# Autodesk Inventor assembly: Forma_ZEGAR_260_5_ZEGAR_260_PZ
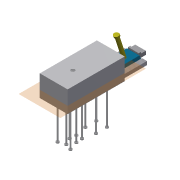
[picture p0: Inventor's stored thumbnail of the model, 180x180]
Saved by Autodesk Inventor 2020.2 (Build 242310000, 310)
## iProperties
Created: 2015-01
Part Number: Forma_ZEGAR_260_5_ZEGAR_260_PZ
Document SubType Name: Assembly
Designer: F.Stasiak
Catalog Web Link: www.expertbooks.pl
Manager: www.cadconsulting.pl
Company: Fabian Stasiak CAD Consulting
Author: F.Stasiak
Subject: Zbiór ćwiczeń. Autodesk Inventor 2020. Kurs Professional
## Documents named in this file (21)
- C:\2020_Kurs_Professional\R6 Formy\Komponenty\Forma_ZEGAR_260_5_ZEGAR_260_PZ.iam
- C:\2020_Kurs_Professional\R6 Formy\Komponenty\Forma_ZEGAR_260_5_ZEGAR_260_MP.ipt
- C:\2020_Kurs_Professional\R6 Formy\Komponenty\Forma_ZEGAR_260_5_ZEGAR_260_WP.ipt
- C:\2020_Kurs_Professional\R6 Formy\Komponenty\Forma_ZEGAR_260_5_ZEGAR_260_CR_Base.ipt
- C:\2020_Kurs_Professional\R6 Formy\Komponenty\Forma_ZEGAR_260_5_ZEGAR_260_CV_Base.ipt
- C:\2020_Kurs_Professional\R6 Formy\Komponenty\Rdzenie formujące\PUNCH_CDH\Forma_ZEGAR_260_5_ZEGAR_260_Rdzeń formujący2_Base.ipt
- C:\2020_Kurs_Professional\R6 Formy\Komponenty\Rdzenie formujące\PUNCH_CDH\Forma_ZEGAR_260_5_ZEGAR_260_Rdzeń formujący2_1.ipt
- C:\2020_Kurs_Professional\R6 Formy\Komponenty\Forma_ZEGAR_260_5_ZEGAR_260_IN1_Base.ipt
- C:\2020_Kurs_Professional\R6 Formy\Komponenty\Forma_ZEGAR_260_5_ZEGAR_260_IN1_1_1.ipt
- C:\2020_Kurs_Professional\R6 Formy\Komponenty\Wypychacze\DME_AH\Grupa EP1.0\Forma_ZEGAR_260_4_ZEGAR_260_Grupa EP1_EP1.ipt
- C:\2020_Kurs_Professional\R6 Formy\Komponenty\Wypychacze\DME_AH\Grupa EP1.0\Forma_ZEGAR_260_4_ZEGAR_260_Grupa EP1_EP2.ipt
- C:\2020_Kurs_Professional\R6 Formy\Komponenty\Wypychacze\DME_AH\Grupa EP1.0\Forma_ZEGAR_260_4_ZEGAR_260_Grupa EP1_EP3.ipt
- C:\2020_Kurs_Professional\R6 Formy\Komponenty\Wypychacze\DME_AH\Grupa EP1.0\Forma_ZEGAR_260_4_ZEGAR_260_Grupa EP1_EP4.ipt
- C:\2020_Kurs_Professional\R6 Formy\Komponenty\Wypychacze\DME_AH\Grupa EP1.0\Forma_ZEGAR_260_4_ZEGAR_260_Grupa EP1_EP5.ipt
- C:\2020_Kurs_Professional\R6 Formy\Komponenty\Wypychacze\DME_AH\Grupa EP1.0\Forma_ZEGAR_260_4_ZEGAR_260_Grupa EP1_EP6.ipt
- C:\2020_Kurs_Professional\R6 Formy\Komponenty\Wypychacze\DME_AH\Grupa EP1.0\Forma_ZEGAR_260_4_ZEGAR_260_Grupa EP1_EP7.ipt
- C:\2020_Kurs_Professional\R6 Formy\Komponenty\Wypychacze\DME_AH\Grupa EP1.0\Forma_ZEGAR_260_4_ZEGAR_260_Grupa EP1_EP8.ipt
- C:\2020_Kurs_Professional\R6 Formy\Komponenty\Wypychacze\DME_AH\Grupa EP1.0\Forma_ZEGAR_260_4_ZEGAR_260_Grupa EP1_EP9.ipt
- C:\2020_Kurs_Professional\R6 Formy\Komponenty\Wypychacze\DME_AH\Grupa EP1.0\Forma_ZEGAR_260_4_ZEGAR_260_Grupa EP1_EP10.ipt
- C:\2020_Kurs_Professional\R6 Formy\Komponenty\Wypychacze\DME_AH\Grupa EP1.0\Forma_ZEGAR_260_4_ZEGAR_260_Grupa EP1_EP11.ipt
- C:\2020_Kurs_Professional\R6 Formy\Komponenty\Suwaki\GENERIC_Zwykła blokada pojedyncza 1 1\Forma_ZEGAR_260_4_ZEGAR_260_SA1.iam
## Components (20 placed, 20 different names)
1. Forma_ZEGAR_260_4_ZEGAR_260_MP:1 — Równoległy:1, Równoległy:2, Równoległy:3, Równoległy:4, Równoległy:5, Równoległy:6
2. Forma_ZEGAR_260_4_ZEGAR_260_WP:1 — Równoległy:4, Równoległy:5, Równoległy:6
3. Forma_ZEGAR_260_4_ZEGAR_260_CR_Base:1 — Równoległy:7, Równoległy:8, Równoległy:9
4. Forma_ZEGAR_260_4_ZEGAR_260_CV_Base:1 — Równoległy:10, Równoległy:11, Równoległy:12
5. Forma_ZEGAR_260_4_ZEGAR_260_Rdzeń formujący2_Base:1 — Kąt:1, Równoległy:20, Równoległy:21, Równoległy:22, Równoległy:23
6. Forma_ZEGAR_260_4_ZEGAR_260_Rdzeń formujący2_1:1 — Równoległy:20, Równoległy:21, Równoległy:22
7. Forma_ZEGAR_260_4_ZEGAR_260_IN1_Base:1 — Równoległy:24, Równoległy:25, Równoległy:26, Równoległy:27, Równoległy:28, Równoległy:29
8. Forma_ZEGAR_260_4_ZEGAR_260_IN1_1_1:1 — Równoległy:27, Równoległy:28, Równoległy:29, Zestawiający:13
9. Forma_ZEGAR_260_4_ZEGAR_260_Grupa EP1_EP1:1 — Zestawiający:2, Równoległy:30, Kąt:2
10. Forma_ZEGAR_260_4_ZEGAR_260_Grupa EP1_EP2:1 — Zestawiający:3, Równoległy:31, Kąt:3
11. Forma_ZEGAR_260_4_ZEGAR_260_Grupa EP1_EP3:1 — Zestawiający:4, Równoległy:32, Kąt:4
12. Forma_ZEGAR_260_4_ZEGAR_260_Grupa EP1_EP4:1 — Zestawiający:5, Równoległy:33, Kąt:5
13. Forma_ZEGAR_260_4_ZEGAR_260_Grupa EP1_EP5:1 — Zestawiający:6, Równoległy:34, Kąt:6
14. Forma_ZEGAR_260_4_ZEGAR_260_Grupa EP1_EP6:1 — Zestawiający:7, Równoległy:35, Kąt:7
15. Forma_ZEGAR_260_4_ZEGAR_260_Grupa EP1_EP7:1 — Zestawiający:8, Równoległy:36, Kąt:8
16. Forma_ZEGAR_260_4_ZEGAR_260_Grupa EP1_EP8:1 — Zestawiający:9, Równoległy:37, Kąt:9
17. Forma_ZEGAR_260_4_ZEGAR_260_Grupa EP1_EP9:1 — Zestawiający:10, Równoległy:38, Kąt:10
18. Forma_ZEGAR_260_4_ZEGAR_260_Grupa EP1_EP10:1 — Zestawiający:11, Równoległy:39, Kąt:11
19. Forma_ZEGAR_260_4_ZEGAR_260_Grupa EP1_EP11:1 — Zestawiający:12, Równoległy:40, Kąt:12
20. Forma_ZEGAR_260_4_ZEGAR_260_SA1:1 [sub-assembly] — Zestawiający:13
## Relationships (57: Flush 33, Angle 12, Mate 12)
- Równoległy:1 [Flush]: Forma_ZEGAR_260_4_ZEGAR_260_MP:1
- Równoległy:2 [Flush]: Forma_ZEGAR_260_4_ZEGAR_260_MP:1
- Równoległy:3 [Flush]: Forma_ZEGAR_260_4_ZEGAR_260_MP:1
- Równoległy:4 [Flush]: Forma_ZEGAR_260_4_ZEGAR_260_MP:1 ↔ Forma_ZEGAR_260_4_ZEGAR_260_WP:1
- Równoległy:5 [Flush]: Forma_ZEGAR_260_4_ZEGAR_260_MP:1 ↔ Forma_ZEGAR_260_4_ZEGAR_260_WP:1
- Równoległy:6 [Flush]: Forma_ZEGAR_260_4_ZEGAR_260_MP:1 ↔ Forma_ZEGAR_260_4_ZEGAR_260_WP:1
- Równoległy:7 [Flush]: Forma_ZEGAR_260_4_ZEGAR_260_CR_Base:1
- Równoległy:8 [Flush]: Forma_ZEGAR_260_4_ZEGAR_260_CR_Base:1
- Równoległy:9 [Flush]: Forma_ZEGAR_260_4_ZEGAR_260_CR_Base:1
- Równoległy:10 [Flush]: Forma_ZEGAR_260_4_ZEGAR_260_CV_Base:1
- Równoległy:11 [Flush]: Forma_ZEGAR_260_4_ZEGAR_260_CV_Base:1
- Równoległy:12 [Flush]: Forma_ZEGAR_260_4_ZEGAR_260_CV_Base:1
- Kąt:1 [Angle]: Forma_ZEGAR_260_4_ZEGAR_260_Rdzeń formujący2_Base:1
- Równoległy:20 [Flush]: Forma_ZEGAR_260_4_ZEGAR_260_Rdzeń formujący2_Base:1 ↔ Forma_ZEGAR_260_4_ZEGAR_260_Rdzeń formujący2_1:1
- Równoległy:21 [Flush]: Forma_ZEGAR_260_4_ZEGAR_260_Rdzeń formujący2_Base:1 ↔ Forma_ZEGAR_260_4_ZEGAR_260_Rdzeń formujący2_1:1
- Równoległy:22 [Flush]: Forma_ZEGAR_260_4_ZEGAR_260_Rdzeń formujący2_Base:1 ↔ Forma_ZEGAR_260_4_ZEGAR_260_Rdzeń formujący2_1:1
- Równoległy:23 [Flush]: Forma_ZEGAR_260_4_ZEGAR_260_Rdzeń formujący2_Base:1
- Równoległy:24 [Flush]: Forma_ZEGAR_260_4_ZEGAR_260_IN1_Base:1
- Równoległy:25 [Flush]: Forma_ZEGAR_260_4_ZEGAR_260_IN1_Base:1
- Równoległy:26 [Flush]: Forma_ZEGAR_260_4_ZEGAR_260_IN1_Base:1
- Równoległy:27 [Flush]: Forma_ZEGAR_260_4_ZEGAR_260_IN1_Base:1 ↔ Forma_ZEGAR_260_4_ZEGAR_260_IN1_1_1:1
- Równoległy:28 [Flush]: Forma_ZEGAR_260_4_ZEGAR_260_IN1_Base:1 ↔ Forma_ZEGAR_260_4_ZEGAR_260_IN1_1_1:1
- Równoległy:29 [Flush]: Forma_ZEGAR_260_4_ZEGAR_260_IN1_Base:1 ↔ Forma_ZEGAR_260_4_ZEGAR_260_IN1_1_1:1
- Zestawiający:2 [Mate]: Forma_ZEGAR_260_4_ZEGAR_260_Grupa EP1_EP1:1
- Równoległy:30 [Flush]: Forma_ZEGAR_260_4_ZEGAR_260_Grupa EP1_EP1:1
- Kąt:2 [Angle]: Forma_ZEGAR_260_4_ZEGAR_260_Grupa EP1_EP1:1
- Zestawiający:3 [Mate]: Forma_ZEGAR_260_4_ZEGAR_260_Grupa EP1_EP2:1
- Równoległy:31 [Flush]: Forma_ZEGAR_260_4_ZEGAR_260_Grupa EP1_EP2:1
- Kąt:3 [Angle]: Forma_ZEGAR_260_4_ZEGAR_260_Grupa EP1_EP2:1
- Zestawiający:4 [Mate]: Forma_ZEGAR_260_4_ZEGAR_260_Grupa EP1_EP3:1
- Równoległy:32 [Flush]: Forma_ZEGAR_260_4_ZEGAR_260_Grupa EP1_EP3:1
- Kąt:4 [Angle]: Forma_ZEGAR_260_4_ZEGAR_260_Grupa EP1_EP3:1
- Zestawiający:5 [Mate]: Forma_ZEGAR_260_4_ZEGAR_260_Grupa EP1_EP4:1
- Równoległy:33 [Flush]: Forma_ZEGAR_260_4_ZEGAR_260_Grupa EP1_EP4:1
- Kąt:5 [Angle]: Forma_ZEGAR_260_4_ZEGAR_260_Grupa EP1_EP4:1
- Zestawiający:6 [Mate]: Forma_ZEGAR_260_4_ZEGAR_260_Grupa EP1_EP5:1
- Równoległy:34 [Flush]: Forma_ZEGAR_260_4_ZEGAR_260_Grupa EP1_EP5:1
- Kąt:6 [Angle]: Forma_ZEGAR_260_4_ZEGAR_260_Grupa EP1_EP5:1
- Zestawiający:7 [Mate]: Forma_ZEGAR_260_4_ZEGAR_260_Grupa EP1_EP6:1
- Równoległy:35 [Flush]: Forma_ZEGAR_260_4_ZEGAR_260_Grupa EP1_EP6:1
- Kąt:7 [Angle]: Forma_ZEGAR_260_4_ZEGAR_260_Grupa EP1_EP6:1
- Zestawiający:8 [Mate]: Forma_ZEGAR_260_4_ZEGAR_260_Grupa EP1_EP7:1
- Równoległy:36 [Flush]: Forma_ZEGAR_260_4_ZEGAR_260_Grupa EP1_EP7:1
- Kąt:8 [Angle]: Forma_ZEGAR_260_4_ZEGAR_260_Grupa EP1_EP7:1
- Zestawiający:9 [Mate]: Forma_ZEGAR_260_4_ZEGAR_260_Grupa EP1_EP8:1
- Równoległy:37 [Flush]: Forma_ZEGAR_260_4_ZEGAR_260_Grupa EP1_EP8:1
- Kąt:9 [Angle]: Forma_ZEGAR_260_4_ZEGAR_260_Grupa EP1_EP8:1
- Zestawiający:10 [Mate]: Forma_ZEGAR_260_4_ZEGAR_260_Grupa EP1_EP9:1
- Równoległy:38 [Flush]: Forma_ZEGAR_260_4_ZEGAR_260_Grupa EP1_EP9:1
- Kąt:10 [Angle]: Forma_ZEGAR_260_4_ZEGAR_260_Grupa EP1_EP9:1
- Zestawiający:11 [Mate]: Forma_ZEGAR_260_4_ZEGAR_260_Grupa EP1_EP10:1
- Równoległy:39 [Flush]: Forma_ZEGAR_260_4_ZEGAR_260_Grupa EP1_EP10:1
- Kąt:11 [Angle]: Forma_ZEGAR_260_4_ZEGAR_260_Grupa EP1_EP10:1
- Zestawiający:12 [Mate]: Forma_ZEGAR_260_4_ZEGAR_260_Grupa EP1_EP11:1
- Równoległy:40 [Flush]: Forma_ZEGAR_260_4_ZEGAR_260_Grupa EP1_EP11:1
- Kąt:12 [Angle]: Forma_ZEGAR_260_4_ZEGAR_260_Grupa EP1_EP11:1
- Zestawiający:13 [Mate]: Forma_ZEGAR_260_4_ZEGAR_260_IN1_1_1:1 ↔ Forma_ZEGAR_260_4_ZEGAR_260_SA1:1
